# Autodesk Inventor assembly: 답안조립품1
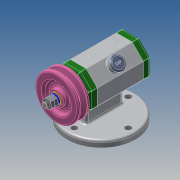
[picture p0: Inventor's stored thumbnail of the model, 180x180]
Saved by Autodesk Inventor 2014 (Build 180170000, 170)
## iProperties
Created: 2021-02
Part Number: 답안조립품1
Document SubType Name: Assembly
Designer: kb542
Author: kb542
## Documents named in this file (14)
- C:\Users\kb542\Desktop\2021.02.20\답안조립품1.iam
- C:\Users\kb542\Desktop\2021.02.20\본체.ipt
- C:\Users\kb542\Desktop\2021.02.20\710204V1018\V벨트풀리.ipt
- C:\Users\kb542\Desktop\2021.02.20\710204V1018\고무캡.ipt
- C:\Users\kb542\Desktop\2021.02.20\710204V1018\너트 M8.ipt
- C:\Users\kb542\Desktop\2021.02.20\710204V1018\뒤커버.ipt
- C:\Users\kb542\Desktop\2021.02.20\710204V1018\베어링 15 x 32 x 9.ipt
- C:\Users\kb542\Desktop\2021.02.20\710204V1018\볼트 M4 x 12.ipt
- C:\Users\kb542\Desktop\2021.02.20\710204V1018\스프링와셔 8.ipt
- C:\Users\kb542\Desktop\2021.02.20\710204V1018\앞커버.ipt
- C:\Users\kb542\Desktop\2021.02.20\710204V1018\오일 실 15 25 7.ipt
- C:\Users\kb542\Desktop\2021.02.20\710204V1018\와셔 8x17.ipt
- C:\Users\kb542\Desktop\2021.02.20\710204V1018\축.ipt
- C:\Users\kb542\Desktop\2021.02.20\710204V1018\키 3 x 3 x 12.ipt
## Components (2 placed, 2 different names)
1. V벨트풀리:1 — 각도:1
2. 고무캡:1
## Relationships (1: Angle 1)
- 각도:1 [Angle]: V벨트풀리:1
